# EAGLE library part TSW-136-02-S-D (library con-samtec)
THROUGH-HOLE .025" SQ POST HEADER Source: Samtec TSW.pdf
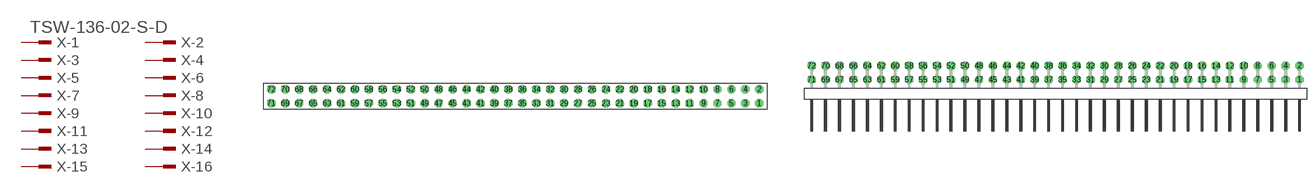
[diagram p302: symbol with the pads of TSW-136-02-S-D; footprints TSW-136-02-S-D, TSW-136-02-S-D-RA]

Designator prefix X; gates -1=MPINV -2=MPIN -3=MPIN -4=MPIN -5=MPIN -6=MPIN -7=MPIN -8=MPIN -9=MPIN -10=MPIN -11=MPIN -12=MPIN -13=MPIN -14=MPIN -15=MPIN -16=MPIN -17=MPIN -18=MPIN -19=MPIN -20=MPIN -21=MPIN -22=MPIN -23=MPIN -24=MPIN -25=MPIN -26=MPIN -27=MPIN -28=MPIN -29=MPIN -30=MPIN -31=MPIN -32=MPIN -33=MPIN -34=MPIN -35=MPIN -36=MPIN -37=MPIN -38=MPIN -39=MPIN -40=MPIN -41=MPIN -42=MPIN -43=MPIN -44=MPIN -45=MPIN -46=MPIN -47=MPIN -48=MPIN -49=MPIN -50=MPIN -51=MPIN -52=MPIN -53=MPIN -54=MPIN -55=MPIN -56=MPIN -57=MPIN -58=MPIN -59=MPIN -60=MPIN -61=MPIN -62=MPIN -63=MPIN -64=MPIN -65=MPIN -66=MPIN -67=MPIN -68=MPIN -69=MPIN -70=MPIN -71=MPIN -72=MPIN

## TSW-136-02-S-D (OC_FARNELL: unknown; OC_NEWARK: unknown)  [TSW-136-02-S-D]
1  -1:1  pas
2  -2:1  pas
3  -3:1  pas
4  -4:1  pas
5  -5:1  pas
6  -6:1  pas
7  -7:1  pas
8  -8:1  pas
9  -9:1  pas
10  -10:1  pas
11  -11:1  pas
12  -12:1  pas
13  -13:1  pas
14  -14:1  pas
15  -15:1  pas
16  -16:1  pas
17  -17:1  pas
18  -18:1  pas
19  -19:1  pas
20  -20:1  pas
21  -21:1  pas
22  -22:1  pas
23  -23:1  pas
24  -24:1  pas
25  -25:1  pas
26  -26:1  pas
27  -27:1  pas
28  -28:1  pas
29  -29:1  pas
30  -30:1  pas
31  -31:1  pas
32  -32:1  pas
33  -33:1  pas
34  -34:1  pas
35  -35:1  pas
36  -36:1  pas
37  -37:1  pas
38  -38:1  pas
39  -39:1  pas
40  -40:1  pas
41  -41:1  pas
42  -42:1  pas
43  -43:1  pas
44  -44:1  pas
45  -45:1  pas
46  -46:1  pas
47  -47:1  pas
48  -48:1  pas
49  -49:1  pas
50  -50:1  pas
51  -51:1  pas
52  -52:1  pas
53  -53:1  pas
54  -54:1  pas
55  -55:1  pas
56  -56:1  pas
57  -57:1  pas
58  -58:1  pas
59  -59:1  pas
60  -60:1  pas
61  -61:1  pas
62  -62:1  pas
63  -63:1  pas
64  -64:1  pas
65  -65:1  pas
66  -66:1  pas
67  -67:1  pas
68  -68:1  pas
69  -69:1  pas
70  -70:1  pas
71  -71:1  pas
72  -72:1  pas

## TSW-136-02-S-D-RA (OC_FARNELL: unknown; OC_NEWARK: unknown)  [TSW-136-02-S-D-RA]
Pads as for TSW-136-02-S-D

## Footprint TSW-136-02-S-D (pad centres in mm)
THROUGH-HOLE .025" SQ POST HEADER Source: Samtec TSW.pdf
drill 1 pad 1.5 octagon: 1 44.45,-1.27; 2 44.45,1.27; 3 41.91,-1.27; 4 41.91,1.27; 5 39.37,-1.27; 6 39.37,1.27; 7 36.83,-1.27; 8 36.83,1.27; 9 34.29,-1.27; 10 34.29,1.27; 11 31.75,-1.27; 12 31.75,1.27; 13 29.21,-1.27; 14 29.21,1.27; 15 26.67,-1.27; 16 26.67,1.27; 17 24.13,-1.27; 18 24.13,1.27; 19 21.59,-1.27; 20 21.59,1.27; 21 19.05,-1.27; 22 19.05,1.27; 23 16.51,-1.27; 24 16.51,1.27; 25 13.97,-1.27; 26 13.97,1.27; 27 11.43,-1.27; 28 11.43,1.27; 29 8.89,-1.27; 30 8.89,1.27; 31 6.35,-1.27; 32 6.35,1.27; 33 3.81,-1.27; 34 3.81,1.27; 35 1.27,-1.27; 36 1.27,1.27; 37 -1.27,-1.27; 38 -1.27,1.27; 39 -3.81,-1.27; 40 -3.81,1.27; 41 -6.35,-1.27; 42 -6.35,1.27; 43 -8.89,-1.27; 44 -8.89,1.27; 45 -11.43,-1.27; 46 -11.43,1.27; 47 -13.97,-1.27; 48 -13.97,1.27; 49 -16.51,-1.27; 50 -16.51,1.27; 51 -19.05,-1.27; 52 -19.05,1.27; 53 -21.59,-1.27; 54 -21.59,1.27; 55 -24.13,-1.27; 56 -24.13,1.27; 57 -26.67,-1.27; 58 -26.67,1.27; 59 -29.21,-1.27; 60 -29.21,1.27; 61 -31.75,-1.27; 62 -31.75,1.27; 63 -34.29,-1.27; 64 -34.29,1.27; 65 -36.83,-1.27; 66 -36.83,1.27; 67 -39.37,-1.27; 68 -39.37,1.27; 69 -41.91,-1.27; 70 -41.91,1.27; 71 -44.45,-1.27; 72 -44.45,1.27

## Footprint TSW-136-02-S-D-RA (pad centres in mm)
THROUGH-HOLE .025" SQ POST HEADER Source: Samtec TSW.pdf
drill 1 pad 1.5 octagon: 1 44.45,1.524; 2 44.45,4.064; 3 41.91,1.524; 4 41.91,4.064; 5 39.37,1.524; 6 39.37,4.064; 7 36.83,1.524; 8 36.83,4.064; 9 34.29,1.524; 10 34.29,4.064; 11 31.75,1.524; 12 31.75,4.064; 13 29.21,1.524; 14 29.21,4.064; 15 26.67,1.524; 16 26.67,4.064; 17 24.13,1.524; 18 24.13,4.064; 19 21.59,1.524; 20 21.59,4.064; 21 19.05,1.524; 22 19.05,4.064; 23 16.51,1.524; 24 16.51,4.064; 25 13.97,1.524; 26 13.97,4.064; 27 11.43,1.524; 28 11.43,4.064; 29 8.89,1.524; 30 8.89,4.064; 31 6.35,1.524; 32 6.35,4.064; 33 3.81,1.524; 34 3.81,4.064; 35 1.27,1.524; 36 1.27,4.064; 37 -1.27,1.524; 38 -1.27,4.064; 39 -3.81,1.524; 40 -3.81,4.064; 41 -6.35,1.524; 42 -6.35,4.064; 43 -8.89,1.524; 44 -8.89,4.064; 45 -11.43,1.524; 46 -11.43,4.064; 47 -13.97,1.524; 48 -13.97,4.064; 49 -16.51,1.524; 50 -16.51,4.064; 51 -19.05,1.524; 52 -19.05,4.064; 53 -21.59,1.524; 54 -21.59,4.064; 55 -24.13,1.524; 56 -24.13,4.064; 57 -26.67,1.524; 58 -26.67,4.064; 59 -29.21,1.524; 60 -29.21,4.064; 61 -31.75,1.524; 62 -31.75,4.064; 63 -34.29,1.524; 64 -34.29,4.064; 65 -36.83,1.524; 66 -36.83,4.064; 67 -39.37,1.524; 68 -39.37,4.064; 69 -41.91,1.524; 70 -41.91,4.064; 71 -44.45,1.524; 72 -44.45,4.064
